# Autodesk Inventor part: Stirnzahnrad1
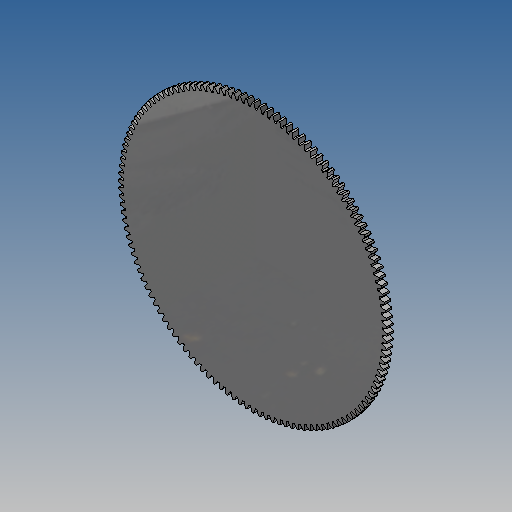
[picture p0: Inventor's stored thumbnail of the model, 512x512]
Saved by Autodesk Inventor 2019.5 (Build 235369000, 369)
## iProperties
Created: 2021-12
Part Number: Stirnzahnrad1
Material: Steel
Document SubType Name: Modeling
Categories: <?xml version="1.0" encoding="UTF-16"?> <MemberInstance><Categories><FamilyTemplate><FamilyTemplateParameter ValueType="xs:double" Id="1" ObjectReferenceKey="da
Mass: 37.542 g
Surface Area: 69.8436 cm^2
Volume: 4.78242 cm^3
Density: 7.85 g/cm^3
Appearance: Steel
CustomPartVersion: 1
Masse: 0,04 kg
Fläche: 7027,12 mm^2
Volumen: 4813,99 mm^3
Abmasse: 65 mm x 65 mm x 1,5 mm
Mass: 0.04
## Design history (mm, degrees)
sketch "Sketch1"
  geometry: C1 r 32.395 at (0, 0)
  constraints: 1 centre point
  dimensions: "d0" = 64.79 diameter of C1 (= da_da)
extrude "Extrusion1" new body sketch "Sketch1" distance "d1" = 1.5 (= da_b); taper "d2" = 0 deg
workplane "Work Plane2"
sketch "Sketch2"
  geometry: C1 r 32.395 at (0, 0) reference; C2 r 32 at (0, 0)
  constraints: 1 centre point, 1 coincident
  dimensions: "d3" = 64 diameter of C2 (= da_dw)
feature "Flankendurchmesser" sketch "Sketch2" dims "d4" = 10, "d5" = 0
workplane "Work Plane8"
workplane "Work Plane9"
feature "Stirnzahnrad" dims "da_b" = 1.5, "da_d" = 64, "da_aw" = 35.5, "da_da" = 64.79, "da_df" = 62.54, "da_dw" = 64, angle "da_beta" = 0 deg, "da_lefttooth" = 0, "da_righttooth" = 0
body "Solid1"
body "Srf1"
other parameters: "d16" = 35.5 (= da_aw), "d17" = 0, "d34" = 0.24544 (computed from da_z), "d39" = 0, "d41" = 0, "d43" = 35.5 (= da_aw), "d46" = 35.5 (= da_aw), "d47" = 0, "d48" = 0
